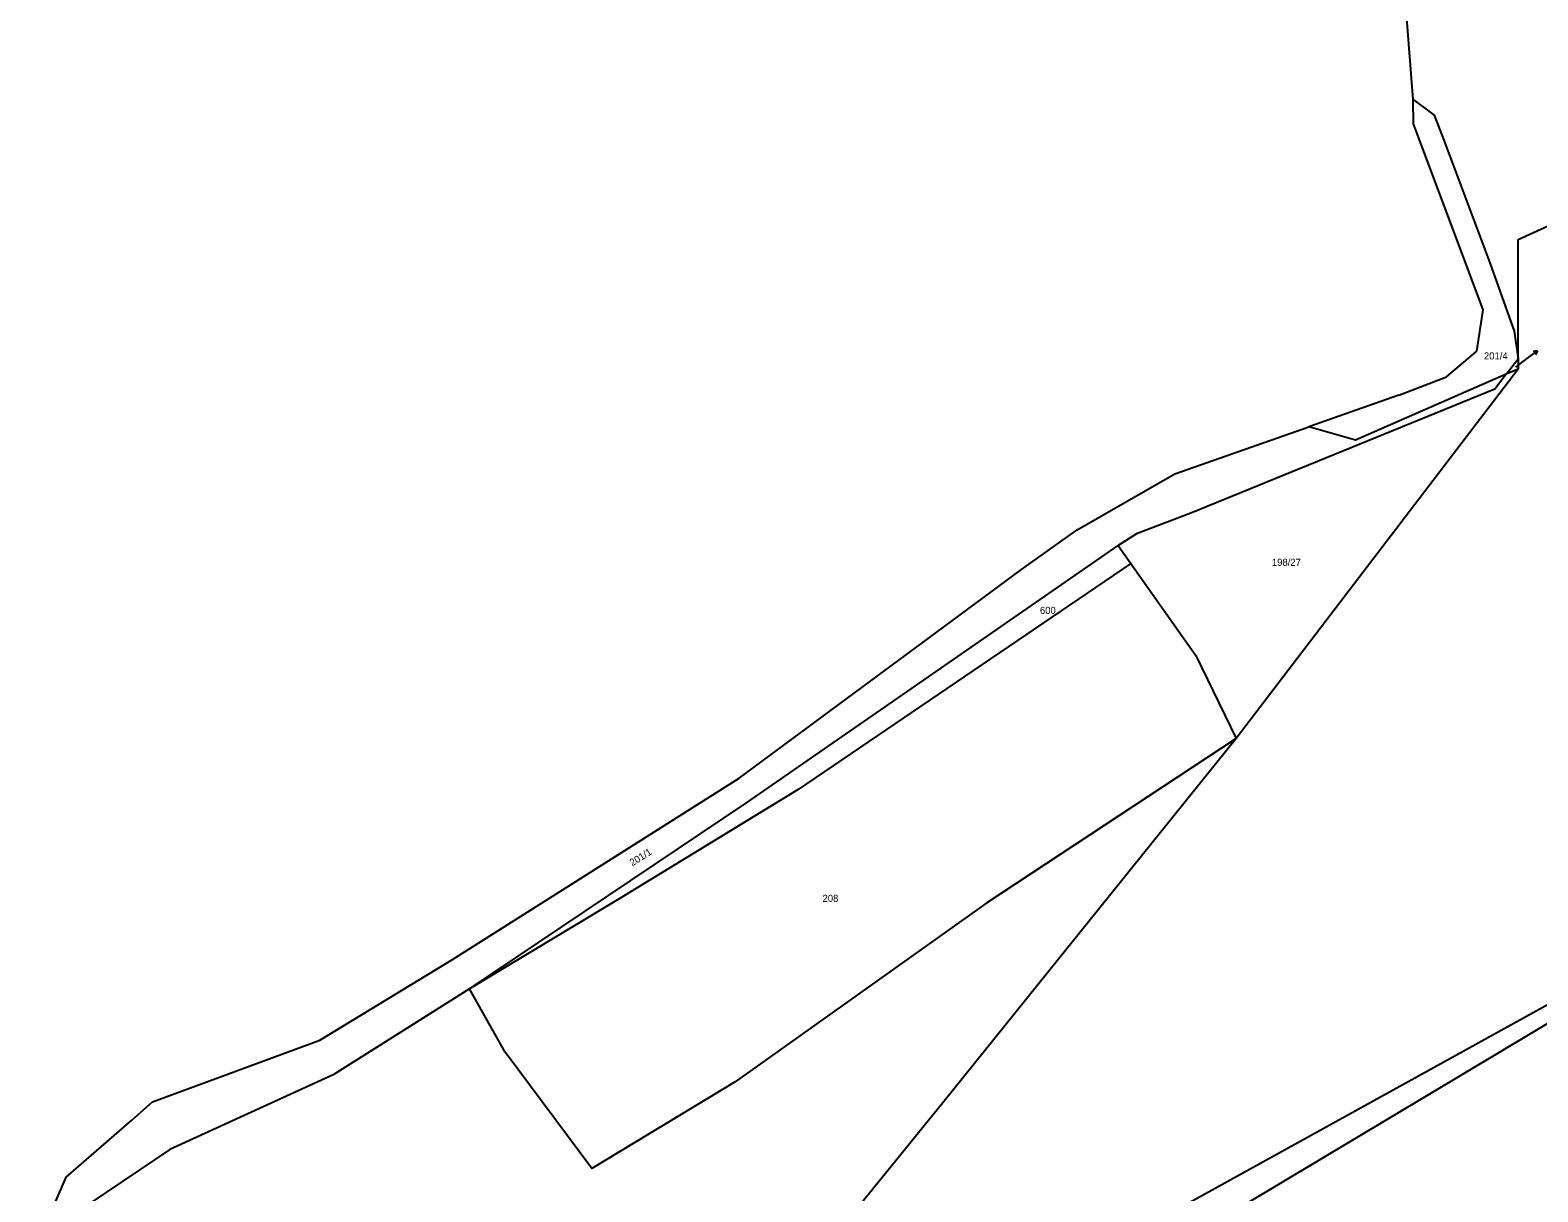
# Model space of a CAD drawing. Extents: x -882150 to -879379, y -1022570 to -1019819.
# Drawn here: x -881038.5 to -880677.3, y -1020727.1 to -1020448.8 of the extents above; entities that cross this region are included whole.
import ezdxf

# ---------------------------------------------------------------- set-up
doc = ezdxf.new("R2010")
doc.units = 0
for name, color, linetype in [('Hranice parcel', 7, 'Continuous'), ('Parcelní čísla', 7, 'Continuous'), ('Pop  PČ popisy', 7, 'Continuous'), ('Vnitřní kresba', 7, 'Continuous')]:
    doc.layers.add(name, color=color, linetype=linetype)

msp = doc.modelspace()

# ---------------------------------------------------------------- linework, layer by layer
at = {"layer": 'Hranice parcel'}
for p, q in [((-880707.2, -1020465.4), (-880708.82, -1020444.91)), ((-880707.07, -1020471.26), (-880707.2, -1020465.4)), ((-880704.73, -1020477.67), (-880707.07, -1020471.26)), ((-880693.89, -1020506.67), (-880704.73, -1020477.67)), ((-880682.01, -1020527.55), (-880682, -1020499)), ((-880690.45, -1020515.83), (-880693.89, -1020506.67)), ((-880691.92, -1020525.75), (-880690.45, -1020515.83)), ((-880699.18, -1020531.9), (-880691.92, -1020525.75)), ((-880682, -1020530), (-880749.6, -1020618.46)), ((-880684.89, -1020531.26), (-880682.01, -1020527.55)), ((-880682, -1020530), (-880684.89, -1020531.26)), ((-880682.01, -1020527.55), (-880682, -1020530)), ((-880710.59, -1020536.26), (-880699.18, -1020531.9)), ((-880710.59, -1020536.26), (-880732.18, -1020543.84)), ((-880801.04, -1020578.02), (-880787.7, -1020568.53)), ((-880777.88, -1020572.27), (-880774.8, -1020576.6)), ((-880749.6, -1020618.46), (-880819.89, -1020705.71))]:
    msp.add_line(p, q, dxfattribs=at)
for points in [[(-880682, -1020499), (-880673.83, -1020495.23), (-880595.38, -1020459.02), (-880526.65, -1020427.3), (-880443.12, -1020388.75), (-880366.39, -1020353.34), (-880317.99, -1020331), (-880274.92, -1020321.12), (-880262.73, -1020318.32)], [(-880707.2, -1020465.4), (-880702.15, -1020469.23), (-880699.87, -1020475.2), (-880688.81, -1020504.53), (-880683.02, -1020520.94), (-880682.01, -1020527.55)], [(-880684.89, -1020531.26), (-880687.63, -1020534.79), (-880760.44, -1020564.55), (-880773.46, -1020569.5), (-880777.88, -1020572.27)], [(-880684.89, -1020531.26), (-880721, -1020547), (-880732.18, -1020543.84)], [(-880787.7, -1020568.53), (-880764.26, -1020555.1), (-880732.18, -1020543.84)], [(-880933.25, -1020678.46), (-880866.89, -1020633.91), (-880777.88, -1020572.27)], [(-880388.55, -1020572.98), (-880500.39, -1020584.08), (-880515.21, -1020588.29), (-880628.31, -1020656.5), (-880820.82, -1020762.82)], [(-880774.8, -1020576.6), (-880854.5, -1020630.67), (-880897.39, -1020656.92), (-880933.25, -1020678.46)], [(-880774.8, -1020576.6), (-880759.25, -1020598.6), (-880749.6, -1020618.46)], [(-881027.55, -1020838.52), (-881029.32, -1020806.45), (-881038.5, -1020743.58), (-881029.85, -1020723.52), (-881014.17, -1020709.89), (-881009.16, -1020705.54), (-880969.13, -1020690.71), (-880937.29, -1020671.41), (-880868.62, -1020627.96), (-880801.04, -1020578.02)], [(-880749.6, -1020618.46), (-880809.33, -1020657.85), (-880869.63, -1020700.73), (-880903.91, -1020721.48), (-880924.69, -1020693.62), (-880933.25, -1020678.46)], [(-880933.25, -1020678.46), (-880965.94, -1020699.04), (-881005.01, -1020716.93), (-881023.92, -1020729.61), (-881028.77, -1020747.18), (-881022.14, -1020805.73), (-881018.96, -1020837.69), (-881016.93, -1020846.3), (-881004.27, -1020862.43), (-880990.66, -1020870.64), (-880964.75, -1020885.05), (-880924.85, -1020905.99), (-880891.74, -1020921.47)], [(-880819.89, -1020705.71), (-880890.41, -1020792.7), (-880891.74, -1020921.47)]]:
    msp.add_lwpolyline(points, dxfattribs=at)
at = {"layer": 'Pop  PČ popisy'}
for p, q in [((-880679.77, -1020527.41), (-880677.373, -1020525.604)), ((-880677.373, -1020525.604), (-880678.474, -1020525.807)), ((-880677.373, -1020525.604), (-880677.872, -1020526.607)), ((-880682.63, -1020529.58), (-880679.77, -1020527.41))]:
    msp.add_line(p, q, dxfattribs=at)
at = {"layer": 'Vnitřní kresba'}
msp.add_line((-880508, -1020587), (-880816, -1020771), dxfattribs=at)

# ---------------------------------------------------------------- texts
at = {"layer": 'Parcelní čísla'}
for s, p in [('201/4', (-880690.24, -1020527.7)), ('198/27', (-880741.03, -1020577.13)), ('600', (-880796.6, -1020588.64)), ('208', (-880848.68, -1020657.61))]:
    msp.add_text(s, height=1.7, dxfattribs=at).set_placement(p)
msp.add_text('201/1', height=1.7, rotation=32, dxfattribs=at).set_placement((-880894.229, -1020649.11))

doc.saveas('drawing.dxf')
